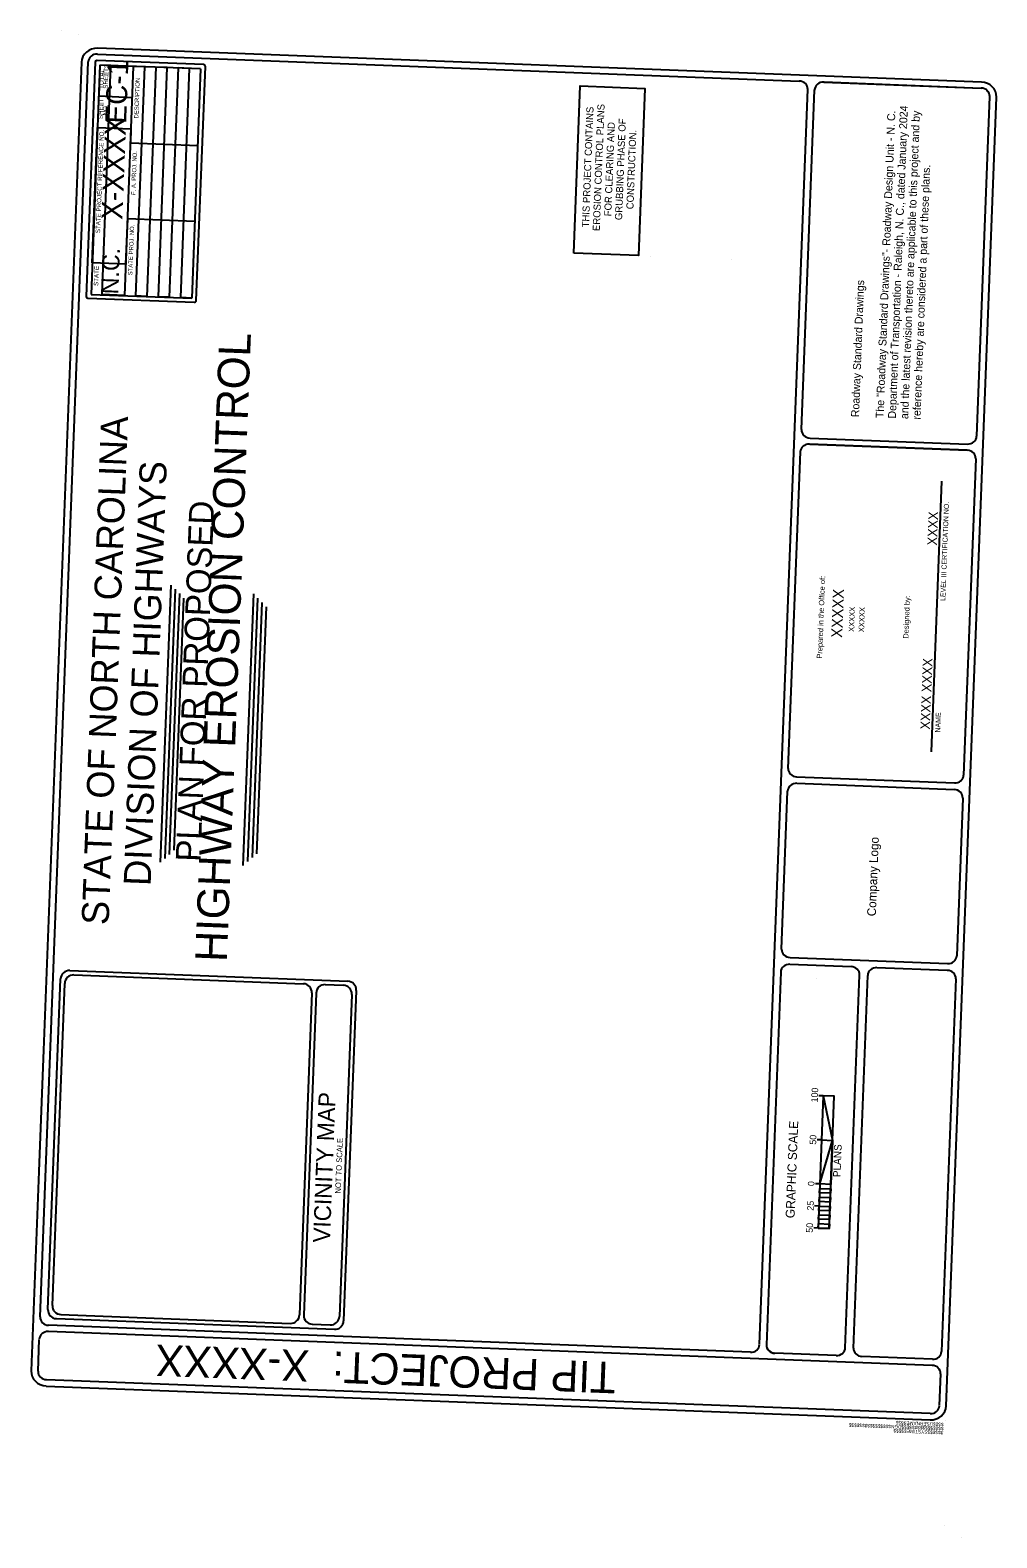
# Model space of a CAD drawing. Extents: x 1654773 to 2116434, y 680831 to 888488.
# Drawn here: x 2109455 to 2114980, y 680831 to 689451 of the extents above; entities that cross this region are included whole.
import ezdxf

# ---------------------------------------------------------------- set-up
doc = ezdxf.new("R2010")
doc.units = 0
for name, color, linetype in [('EC Title Sheet CELL', 7, 'Continuous'), ('EC Title Sheet Consultant CELL', 7, 'Continuous'), ('Old_Level_1', 7, 'Continuous'), ('Old_Level_18', 7, 'Continuous'), ('Old_Level_38', 7, 'Continuous')]:
    doc.layers.add(name, color=color, linetype=linetype)

msp = doc.modelspace()

# ---------------------------------------------------------------- linework, layer by layer
at = {"layer": 'EC Title Sheet CELL'}
for p, q in [((2109633, 689451.5), (2109633, 689451.5)), ((2109732, 689425.1), (2109732, 689425.1)), ((2109839, 689314.6), (2113850.5, 689160.7)), ((2114891.8, 689154.3), (2109841.3, 689348.2)), ((2109511.5, 682095.3), (2109786.9, 689269.9)), ((2109826.2, 689269.4), (2109774.7, 687928.8)), ((2109852.7, 689251.5), (2109802.4, 687940.9)), ((2110445.4, 689254.4), (2109836.5, 689278.3)), ((2109852.7, 689251.5), (2109846.9, 689075.2)), ((2109916.2, 689249.2), (2109852.7, 689251.5)), ((2110429.1, 689229.4), (2109852.7, 689251.5)), ((2109865.8, 687939.3), (2109916.2, 689249.2)), ((2110043.8, 689244.3), (2109993.5, 687934.4)), ((2110109.2, 689241.8), (2110043.8, 689244.3)), ((2110058.9, 687931.9), (2110109.2, 689241.8)), ((2110172.5, 689239.2), (2110122.3, 687928.5)), ((2110238, 689237.6), (2110172.5, 689239.2)), ((2110187.7, 687927), (2110238, 689237.6)), ((2110300.3, 689235.3), (2110250, 687924.6)), ((2110365.7, 689232.7), (2110300.3, 689235.3)), ((2110315.4, 687922.1), (2110365.7, 689232.7)), ((2110429.1, 689229.4), (2110378.8, 687918.7)), ((2110403.8, 687905.6), (2110456.1, 689243.6)), ((2113990.2, 689154.3), (2114890.5, 689119.8)), ((2113992.3, 689155.2), (2114890.5, 689119.8)), ((2109846.9, 689075.2), (2110037, 689066.9)), ((2113623.6, 681937.5), (2113898.9, 689112.1)), ((2113863.6, 687168.4), (2113938.2, 689110.5)), ((2114939, 689071.3), (2114864.5, 687130)), ((2109809.3, 688120.9), (2109840, 688895.1)), ((2109840, 688895.1), (2110030.2, 688887.8)), ((2110030.2, 688887.8), (2110027.1, 688807.6)), ((2110027.1, 688807.6), (2110412.3, 688792.8)), ((2110010.3, 688372), (2110000.4, 688113.5)), ((2110395.6, 688357.2), (2110010.3, 688372)), ((2110000.4, 688113.5), (2109809.3, 688120.9)), ((2113000.1, 688159.6), (2113000.1, 688159.6)), ((2113461.7, 688141.8), (2113461.7, 688141.8)), ((2109784.4, 687919.1), (2110392.4, 687895.7)), ((2109802.4, 687940.9), (2110378.7, 687918.7)), ((2109993.5, 687934.4), (2109865.8, 687939.3)), ((2110122.3, 687928.5), (2110058.9, 687931.9)), ((2110250, 687924.6), (2110187.7, 687927)), ((2110378.8, 687918.7), (2110315.4, 687922.1)), ((2114811, 687049.8), (2113908.7, 687084.4)), ((2113910.7, 687084.4), (2114811, 687049.8)), ((2113912.1, 687118.9), (2114812.3, 687084.3)), ((2113787.3, 685230.7), (2113856.8, 687039.7)), ((2114859.5, 687000.8), (2114790.1, 685192.2)), ((2110199.6, 684693.7), (2110260.4, 686278.6)), ((2110225.6, 684716), (2110284.6, 686254.4)), ((2110251.7, 684738.4), (2110309.9, 686230.9)), ((2110277.8, 684762.7), (2110333, 686203)), ((2110672.5, 684675.5), (2110732.1, 686227.8)), ((2110698.6, 684697.9), (2110756.3, 686203.5)), ((2110724.6, 684720.3), (2110780.6, 686179.2)), ((2110750.7, 684742.6), (2110804.8, 686155)), ((2113835.8, 685182.1), (2114738, 685147.5)), ((2113749.6, 684197.8), (2113784.2, 685100.5)), ((2113836.4, 685145.2), (2114736.6, 685109.7)), ((2114785.1, 685061.1), (2114750.4, 684159.4)), ((2113798.1, 684149.2), (2114698.4, 684114.7)), ((2113744.6, 684065.6), (2113662.7, 681935.1)), ((2113796.6, 684110.3), (2114147.1, 684097)), ((2114113.7, 681918), (2114195.6, 684048.4)), ((2114160.3, 681916.3), (2114242.2, 684046.6)), ((2114294.3, 684091.3), (2114696.9, 684075.9)), ((2113951.3, 684028.3), (2113951.3, 684028.3)), ((2114745.4, 684027.3), (2114663.6, 681896.7)), ((2109511.5, 682095.3), (2109511.5, 682095.3)), ((2109460.6, 682027.7), (2109460.6, 682027.7)), ((2109499.5, 681783.8), (2109506.5, 681965.7)), ((2114610.2, 681816.5), (2109558.6, 682011.3)), ((2113571.4, 681891.8), (2109560.1, 682046.8)), ((2114061.6, 681873.5), (2113711.3, 681886.4)), ((2109454.5, 681868.5), (2109454.5, 681868.5)), ((2114611.5, 681851.9), (2114208.8, 681867.7)), ((2114599.6, 681542.3), (2109548.1, 681735.2)), ((2114652.8, 681587), (2114659.7, 681768.8)), ((2114700.1, 681667.2), (2114700.1, 681667.2)), ((2114687.7, 681501.5), (2114687.7, 681501.5)), ((2114683.2, 680899.8), (2114683.2, 680899.8)), ((2114780.6, 680831.1), (2114780.6, 680831.1))]:
    msp.add_line(p, q, dxfattribs=at)
for points in [[(2109747.5, 689267.6), (2109460.4, 681785.3)], [(2114690.9, 681584.5), (2114978.1, 689067.8)], [(2109546.7, 681698.8), (2114598.2, 681505.8)]]:
    msp.add_lwpolyline(points, dxfattribs=at)
msp.add_lwpolyline([(2112562.6, 688176.4), (2112599.2, 689132.6), (2112967.8, 689118.4), (2112931.1, 688162.2)], close=True, dxfattribs=at)
for centre, major_axis, ratio, start_param, end_param in [((2109838, 689264.2), (-90.5, 3.5), 0.927398, 4.712389, 6.283185), ((2109837.2, 689268), (-50.3, 1.9), 0.927398, 4.712389, 6.283185), ((2109836.2, 689269), (-10.1, 0.4), 0.927398, 4.712389, 6.283185), ((2109837.3, 689267.5), (-11.1, 0.4), 0.927398, 4.712389, 6.283185), ((2110445, 689244), (-11.1, 0.4), 0.93232, 3.141593, 4.712389), ((2113848.6, 689114), (50.3, -1.9), 0.927398, 0, 1.570796), ((2113988.5, 689108.2), (-50.3, 1.9), 0.927398, 4.712389, 6.283185), ((2113989.7, 689107.2), (-51.4, 2), 0.927399, 4.712389, 6.283185), ((2113989.7, 689107.2), (-51.4, 2), 0.927399, 4.712389, 6.283185), ((2114888.8, 689073.7), (50.3, -1.9), 0.927398, 0, 1.570796), ((2114888.7, 689071.8), (-89.5, 3.4), 0.927398, 3.141593, 4.712389), ((2109784.8, 687928.4), (10.1, -0.4), 0.927398, 3.141593, 4.712389), ((2110392.7, 687906), (11.1, -0.4), 0.927398, 4.712389, 6.283185), ((2113914, 687166), (-50.3, 1.9), 0.927398, 0, 1.570796), ((2113907, 687037.8), (-50.3, 1.9), 0.927398, 4.712389, 6.283185), ((2114809.3, 687002.7), (-50.3, 1.9), 0.927398, 3.141593, 4.712389), ((2114814.3, 687131.5), (50.3, -1.9), 0.927398, 4.712389, 6.283185), ((2113837.6, 685228.8), (-50.3, 1.9), 0.927398, 6.282622, 7.852769), ((2114739.8, 685194.1), (50.3, -1.9), 0.927398, 4.712389, 6.283185), ((2113834.5, 685098.6), (-50.3, 1.9), 0.927398, 4.711278, 6.283185), ((2114734.8, 685063.1), (50.3, -1.9), 0.927398, 0, 1.570092), ((2113799.9, 684195.8), (50.3, -1.9), 0.927398, 3.141593, 4.712389), ((2114700.2, 684161.3), (50.3, -1.9), 0.927398, 4.712389, 6.283185), ((2113794.8, 684063.7), (-50.3, 1.9), 0.927398, 4.712389, 6.283185), ((2114145.3, 684050.3), (50.3, -1.9), 0.927398, 0, 1.570796), ((2114292.5, 684044.7), (-50.3, 1.9), 0.927398, 4.712389, 6.283185), ((2114695.1, 684029.2), (50.3, -1.9), 0.927398, 0, 1.570796), ((2109561.9, 682093), (-50.3, 1.9), 0.927398, 0, 1.570796), ((2109557, 681964.2), (-50.3, 1.9), 0.927398, 4.712389, 6.283185), ((2113573.4, 681939), (50.3, -1.9), 0.927398, 4.712389, 6.283185), ((2113713.1, 681933.1), (50.3, -1.9), 0.927398, 3.141593, 4.712389), ((2113713.2, 681933.6), (-50.3, 1.9), 0.927398, 0, 1.570796), ((2114063.4, 681920.2), (50.3, -1.9), 0.927398, 4.712389, 6.283185), ((2114210.6, 681914.3), (-50.3, 1.9), 0.927398, 0, 1.570796), ((2114613.3, 681898.6), (50.3, -1.9), 0.927398, 4.712389, 6.283185), ((2114608.5, 681770.3), (-50.3, 1.9), 0.927398, 3.141593, 4.712389), ((2109550, 681782.3), (-89.5, 3.4), 0.927398, 0, 1.570796), ((2109550, 681782.3), (-89.5, 3.4), 0.927398, 0, 1.570796), ((2109550, 681782.3), (-50.3, 1.9), 0.927398, 0, 1.570796), ((2114601.5, 681588.4), (89.5, -3.4), 0.927398, 4.712389, 6.283185), ((2114601.5, 681588.4), (50.3, -1.9), 0.927398, 4.712389, 6.283185)]:
    msp.add_ellipse(centre, major_axis=major_axis, ratio=ratio, start_param=start_param, end_param=end_param, dxfattribs=at)
at = {"layer": 'EC Title Sheet Consultant CELL'}
msp.add_line((2114605.6, 685325.6), (2114664.9, 686871.9), dxfattribs=at)
at = {"layer": 'Old_Level_1'}
for p, q in [((2113987.9, 683358.1), (2113958.9, 682602.5)), ((2113987.9, 683358.1), (2113962.8, 683359)), ((2114050.9, 683355.6), (2113987.9, 683358.1)), ((2114021.9, 682600.1), (2114050.9, 683355.6)), ((2113978.3, 683106.2), (2113953.1, 683107.2)), ((2113978.3, 683106.2), (2114041.2, 683103.8)), ((2113968.6, 682854.4), (2113943.4, 682855.3)), ((2113963.8, 682728.4), (2113938.6, 682729.4)), ((2113958.9, 682602.5), (2113933.8, 682603.5)), ((2113933.8, 682603.5), (2113933.8, 682603.5)), ((2113958.9, 682602.5), (2114021.9, 682600.1)), ((2113958.9, 682602.5), (2113958.9, 682602.5))]:
    msp.add_line(p, q, dxfattribs=at)
at = {"layer": 'Old_Level_18'}
for p, q in [((2109680.9, 684074.8), (2111270.2, 684013.8)), ((2109704.3, 684049.5), (2111016.1, 683999.1)), ((2109556, 682136.7), (2109628.6, 684026.4)), ((2109581.4, 682160.2), (2109652, 684001)), ((2111064.5, 683946.8), (2110993.9, 682106)), ((2111088.9, 683945.9), (2111018.2, 682105)), ((2111141.2, 683994.3), (2111244.5, 683990.4)), ((2111318.6, 683961.5), (2111246.1, 682071.9)), ((2111292.9, 683938.1), (2111222.3, 682097.2)), ((2109604.5, 682084.4), (2111193.8, 682023.4)), ((2109629.8, 682107.9), (2110941.6, 682057.5)), ((2111066.7, 682052.7), (2111170, 682048.8))]:
    msp.add_line(p, q, dxfattribs=at)
for centre, start, end in [((2109678.9, 684024.4), 87.80197, 177.80198), ((2109702.4, 683999.1), 87.80199, 177.80199), ((2111014.2, 683948.8), 357.80199, 87.80198), ((2111139.3, 683944), 87.80195, 177.80201), ((2111242.6, 683940), 357.80201, 87.80195), ((2111268.3, 683963.4), 357.80201, 87.80196), ((2109606.4, 682134.8), 177.80197, 267.80194), ((2109631.7, 682158.2), 177.80198, 267.80194), ((2110943.5, 682107.9), 267.80197, 357.80201), ((2111068.6, 682103.1), 177.80201, 267.80195), ((2111171.9, 682099.1), 267.80195, 357.80201), ((2111195.8, 682073.8), 267.80192, 357.80201)]:
    msp.add_arc(centre, 50.4, start, end, dxfattribs=at)
at = {"layer": 'Old_Level_38'}
msp.add_line((2113965.7, 682778.8), (2114028.7, 682776.4), dxfattribs=at)
for points in [[(2113987.9, 683358.1), (2114041.2, 683103.8), (2114050.9, 683355.6)], [(2113968.6, 682854.4), (2114041.2, 683103.8), (2114031.6, 682851.9)], [(2113966.7, 682804), (2113967.6, 682829.2), (2114030.6, 682826.8), (2114029.6, 682801.6)], [(2113964.7, 682753.6), (2113965.7, 682778.8), (2114028.7, 682776.4), (2114027.7, 682751.2)], [(2113960.9, 682652.9), (2113961.8, 682678.1), (2114024.8, 682675.7), (2114023.8, 682650.5)], [(2113962.8, 682703.3), (2113963.8, 682728.4), (2114026.7, 682726), (2114025.8, 682700.8)], [(2113958.9, 682602.5), (2113959.9, 682627.7), (2114022.9, 682625.3), (2114021.9, 682600.1)]]:
    msp.add_lwpolyline(points, close=True, dxfattribs=at)

# ---------------------------------------------------------------- texts
at = {"layer": 'EC Title Sheet CELL'}
for s, height, rotation, p in [('TOTAL', 25.7, 87.80201, (2109872.6, 689115.3)), ('SHEETS', 25.7, 87.80201, (2109897.8, 689116.2)), ('EC-1', 119.85, 87.80201, (2110002.8, 688915.5)), ('DESCRIPTION', 24.672, 87.80201, (2110072.7, 688945.9)), ('SHEET', 25.7, 87.80201, (2109869.1, 688942.6)), ('X-XXXX', 119.85, 87.80201, (2109981.6, 688365.6)), ('NO.', 25.7, 87.80201, (2109895, 688963.1)), ('THIS PROJECT CONTAINS', 40.763, 87.80201, (2112648.6, 688323)), ('EROSION CONTROL PLANS', 40.763, 87.80201, (2112710.3, 688302.1)), ('GRUBBING PHASE OF', 40.763, 87.80201, (2112837.7, 688364.6)), ('The "Roadway Standard Drawings"- Roadway Design Unit - N. C.', 45.303, 87.80201, (2114332.6, 687232.5)), ('Department of Transportation - Raleigh, N. C., dated January 2024', 45.303, 87.80201, (2114402.9, 687229.8)), ('and the latest revision thereto are applicable to this project and by', 45.303, 87.80201, (2114473.2, 687227.1)), ('STATE PROJECT REFERENCE NO.', 25.699, 87.80201, (2109854, 688290.2)), ('FOR CLEARING AND', 40.763, 87.80201, (2112776.1, 688386.6)), ('CONSTRUCTION.', 40.763, 87.80201, (2112902.7, 688426.7)), ('F. A. PROJ. NO.', 24.672, 87.80201, (2110055.8, 688508.5)), ('reference hereby are considered a part of these plans.', 45.303, 87.80201, (2114543.5, 687224.4)), ('STATE PROJ. NO.', 24.672, 87.80201, (2110038.2, 688049.5)), ('N.C.', 99.5, 87.80201, (2109958.4, 687939.5)), ('STATE', 25.7, 87.80201, (2109843.4, 687988.8)), ('Roadway Standard Drawings', 45.303, 87.80201, (2114192, 687237.9)), ('HIGHWAY EROSION CONTROL', 181.41, 87.80201, (2110578.7, 684121.9)), ('STATE OF NORTH CAROLINA', 154.267, 87.80201, (2109902.7, 684333.2)), ('DIVISION OF HIGHWAYS', 154.267, 87.80201, (2110142.9, 684556.7)), ('PLAN FOR PROPOSED', 141.082, 87.80201, (2110427.4, 684694.9)), ('LEVEL III CERTIFICATION NO.', 28.888, 87.80201, (2114685.3, 686187.4)), ('XXXX', 54.36, 87.80201, (2114637.2, 686504.6)), ('Prepared in the Office of:', 30.845, 87.80201, (2113981.2, 685857.6)), ('XXXXX', 62.66, 87.80201, (2114095.6, 685975.9)), ('Designed by:', 30.845, 87.80201, (2114474.5, 685971.5)), ('XXXXX', 31.21, 87.80201, (2114164, 686010.7)), ('XXXXX', 31.21, 87.80201, (2114220.7, 686008.5)), ('XXXX XXXX', 54.36, 87.80201, (2114596.8, 685451.7)), ('NAME', 28.89, 87.80201, (2114656, 685435.1)), ('GRAPHIC SCALE', 51.338, 87.80201, (2113823.7, 682657.8)), ('TIP PROJECT:  X-XXXX', 178.831, 177.80201, (2112804.8, 681835.4)), ('$$$$$$$$$$$$$$$$DGN$$$$$$$$$$$$$$$$', 19.604, 177.80201, (2114676.3, 681465.6)), ('$$$$$$SYSTIME$$$$$', 19.604, 177.80201, (2114674.4, 681442.3)), ('$$$$USERNAME$$$$', 19.604, 177.80201, (2114676.2, 681488.8))]:
    msp.add_text(s, height=height, rotation=rotation, dxfattribs=at).set_placement(p)
at = {"layer": 'EC Title Sheet Consultant CELL'}
msp.add_text('Company Logo', height=49.995, rotation=87.80201, dxfattribs=at).set_placement((2114288.3, 684384.3))
at = {"layer": 'Old_Level_1'}
for s, height, p in [('VICINITY MAP', 96.543, (2111167.8, 682517.2)), ('NOT TO SCALE', 32.52, (2111229.9, 682798.7)), ('PLANS', 42.84, (2114086.1, 682892.7))]:
    msp.add_text(s, height=height, rotation=87.80201, dxfattribs=at).set_placement(p)
at = {"layer": 'Old_Level_38'}
for s, p in [('100', (2113956.2, 683320)), ('50', (2113947, 683078.6)), ('0', (2113937.1, 682841.7)), ('25', (2113932.5, 682701.4)), ('50', (2113927.6, 682574.9))]:
    msp.add_text(s, height=37.8, rotation=87.80201, dxfattribs=at).set_placement(p)

doc.saveas('drawing.dxf')
